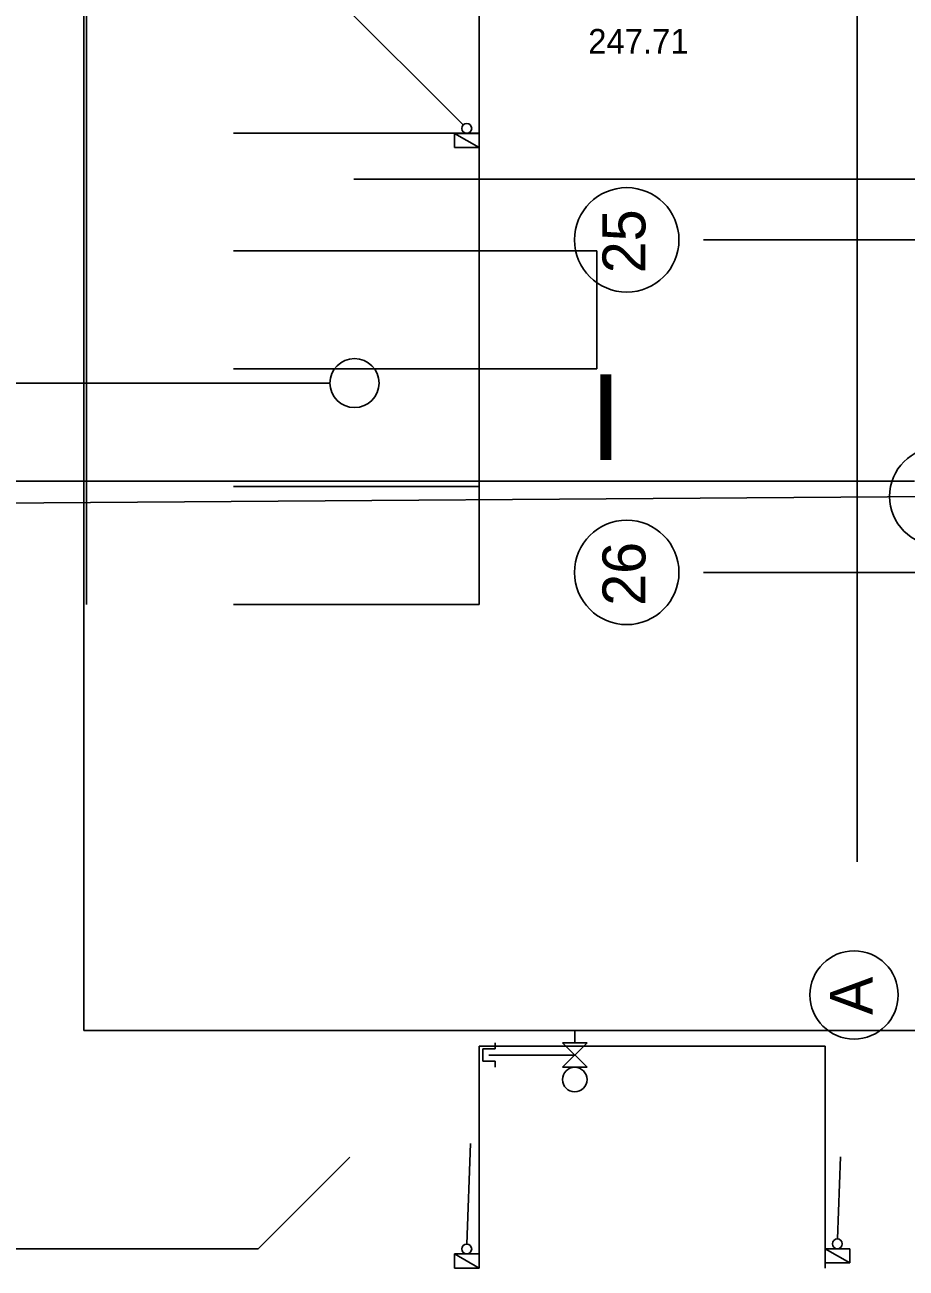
# Model space of a CAD drawing. Extents: x -264205 to -263659, y -1242401 to -1242060.
# Drawn here: x -263925.35 to -263907.39, y -1242254.98 to -1242229.65 of the extents above; entities that cross this region are included whole.
import ezdxf

# ---------------------------------------------------------------- set-up
doc = ezdxf.new("R2010")
doc.units = 0
for name, color, linetype in [('BOD_VYSKA', 7, 'Continuous'), ('KFA_SO_40-2-II_DAZDOVA_KANALIZACIA', 7, 'Continuous'), ('OBRUBNIKY_KOMUNIKACIE_PROJEKT', 7, 'Continuous'), ('OSI_STAVBY_KFA', 7, 'Continuous'), ('SITUACIA_DSP_2D', 7, 'Continuous'), ('TDZ_VODOROVNE_PROJEKT', 7, 'Continuous')]:
    doc.layers.add(name, color=color, linetype=linetype)

msp = doc.modelspace()

# ---------------------------------------------------------------- linework, layer by layer
at = {"layer": 'KFA_SO_40-2-II_DAZDOVA_KANALIZACIA'}
msp.add_line((-263926.723, -1242239.4), (-263906.731, -1242239.259), dxfattribs=at)
msp.add_circle((-263906.731, -1242239.259), 1, dxfattribs=at)
at = {"layer": 'OBRUBNIKY_KOMUNIKACIE_PROJEKT'}
for p, q in [((-263916.093, -1242234.257), (-263913.693, -1242234.257)), ((-263916.093, -1242236.657), (-263916.093, -1242234.257)), ((-263913.693, -1242234.257), (-263913.693, -1242236.657)), ((-263913.693, -1242236.657), (-263916.093, -1242236.657)), ((-263916.093, -1242254.982), (-263916.093, -1242250.458)), ((-263916.093, -1242250.458), (-263909.043, -1242250.458)), ((-263909.043, -1242250.458), (-263909.043, -1242254.982))]:
    msp.add_line(p, q, dxfattribs=at)
at = {"layer": 'OSI_STAVBY_KFA'}
for p, q in [((-263908.393, -1242083.237), (-263908.393, -1242246.707)), ((-263792.653, -1242234.032), (-263911.523, -1242234.032)), ((-263792.653, -1242240.807), (-263911.523, -1242240.807))]:
    msp.add_line(p, q, dxfattribs=at)
for centre, radius in [((-263913.085, -1242234.032), 1.064), ((-263913.085, -1242240.807), 1.064), ((-263908.453, -1242249.416), 0.899)]:
    msp.add_circle(centre, radius, dxfattribs=at)
at = {"layer": 'SITUACIA_DSP_2D'}
for p, q in [((-263924.143, -1242185.14), (-263924.143, -1242250.14)), ((-263916.414, -1242231.691), (-263926.24, -1242221.865)), ((-263916.593, -1242231.862), (-263916.093, -1242231.862)), ((-263916.593, -1242232.152), (-263916.593, -1242231.862)), ((-263916.593, -1242231.862), (-263916.093, -1242232.152)), ((-263916.593, -1242231.862), (-263916.093, -1242232.152)), ((-263916.093, -1242231.862), (-263916.593, -1242231.862)), ((-263916.093, -1242231.862), (-263916.093, -1242232.152)), ((-263916.093, -1242232.152), (-263916.093, -1242231.862)), ((-263916.093, -1242232.152), (-263916.593, -1242232.152)), ((-263905.894, -1242232.793), (-263918.643, -1242232.793)), ((-263916.093, -1242234.257), (-263913.693, -1242234.257)), ((-263916.093, -1242236.657), (-263916.093, -1242234.257)), ((-263913.693, -1242234.257), (-263913.693, -1242236.657)), ((-263913.693, -1242236.657), (-263916.093, -1242236.657)), ((-263919.13, -1242236.949), (-263926.43, -1242236.949)), ((-263907.219, -1242238.949), (-263926.43, -1242238.949)), ((-263924.143, -1242250.14), (-263822.79, -1242250.14)), ((-263914.143, -1242250.14), (-263914.143, -1242250.39)), ((-263914.143, -1242250.14), (-263914.143, -1242250.39)), ((-263916.093, -1242254.982), (-263916.093, -1242250.458)), ((-263916.093, -1242250.458), (-263909.043, -1242250.458)), ((-263916.018, -1242250.515), (-263915.768, -1242250.515)), ((-263916.018, -1242250.765), (-263916.018, -1242250.515)), ((-263915.768, -1242250.515), (-263915.768, -1242250.39)), ((-263914.393, -1242250.39), (-263913.893, -1242250.89)), ((-263913.893, -1242250.39), (-263914.393, -1242250.39)), ((-263914.393, -1242250.89), (-263913.893, -1242250.39)), ((-263909.043, -1242250.458), (-263909.043, -1242254.982)), ((-263915.768, -1242250.765), (-263916.018, -1242250.765)), ((-263914.143, -1242250.64), (-263915.893, -1242250.64)), ((-263915.768, -1242250.89), (-263915.768, -1242250.765)), ((-263913.893, -1242250.89), (-263914.393, -1242250.89)), ((-263916.339, -1242254.492), (-263916.265, -1242252.443)), ((-263920.595, -1242254.592), (-263918.723, -1242252.72)), ((-263908.789, -1242254.387), (-263908.729, -1242252.715)), ((-263929.73, -1242254.592), (-263920.595, -1242254.592)), ((-263909.043, -1242254.587), (-263908.543, -1242254.587)), ((-263909.043, -1242254.877), (-263909.043, -1242254.587)), ((-263909.043, -1242254.587), (-263908.543, -1242254.877)), ((-263909.043, -1242254.587), (-263908.543, -1242254.877)), ((-263908.543, -1242254.587), (-263909.043, -1242254.587)), ((-263908.543, -1242254.587), (-263908.543, -1242254.877)), ((-263908.543, -1242254.877), (-263908.543, -1242254.587)), ((-263916.593, -1242254.692), (-263916.093, -1242254.692)), ((-263916.593, -1242254.982), (-263916.593, -1242254.692)), ((-263916.593, -1242254.692), (-263916.093, -1242254.982)), ((-263916.593, -1242254.692), (-263916.093, -1242254.982)), ((-263916.093, -1242254.692), (-263916.593, -1242254.692)), ((-263916.093, -1242254.692), (-263916.093, -1242254.982)), ((-263916.093, -1242254.982), (-263916.093, -1242254.692)), ((-263908.543, -1242254.877), (-263909.043, -1242254.877)), ((-263916.093, -1242254.982), (-263916.593, -1242254.982))]:
    msp.add_line(p, q, dxfattribs=at)
for centre, radius in [((-263916.343, -1242231.762), 0.1), ((-263918.63, -1242236.949), 0.5), ((-263914.143, -1242251.14), 0.25), ((-263908.793, -1242254.487), 0.1), ((-263916.343, -1242254.592), 0.1)]:
    msp.add_circle(centre, radius, dxfattribs=at)
at = {"layer": 'TDZ_VODOROVNE_PROJEKT'}
for p, q in [((-263924.088, -1242241.458), (-263924.093, -1242087.307)), ((-263916.093, -1242187.557), (-263916.093, -1242241.458)), ((-263921.093, -1242231.857), (-263916.093, -1242231.857)), ((-263921.093, -1242234.257), (-263916.093, -1242234.257)), ((-263921.093, -1242236.657), (-263916.093, -1242236.657)), ((-263921.093, -1242239.057), (-263916.093, -1242239.057)), ((-263921.093, -1242241.458), (-263916.093, -1242241.458))]:
    msp.add_line(p, q, dxfattribs=at)

# ---------------------------------------------------------------- texts
at = {"layer": 'BOD_VYSKA'}
msp.add_text('247.71', height=0.5, dxfattribs=at).set_placement((-263913.869, -1242230.235))
at = {"layer": 'OSI_STAVBY_KFA'}
for s, p in [('25', (-263912.704, -1242234.712)), ('26', (-263912.704, -1242241.487)), ('A', (-263908.072, -1242249.824))]:
    msp.add_text(s, height=0.875, rotation=90, dxfattribs=at).set_placement(p)
at = {"layer": 'SITUACIA_DSP_2D'}
msp.add_text('I', height=1.75, dxfattribs=at).set_placement((-263913.835, -1242238.519))

doc.saveas('drawing.dxf')
